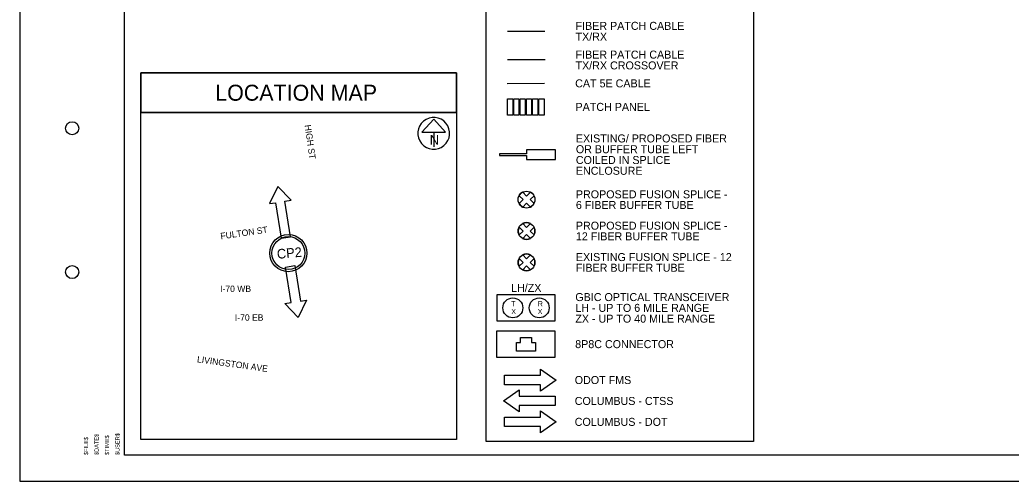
# Model space of a CAD drawing. Extents: x 1805893 to 1833564, y 708898 to 716199.
# Drawn here: x 1831322.5 to 1831701.4, y 713257.9 to 713434.4 of the extents above; entities that cross this region are included whole.
import ezdxf

# ---------------------------------------------------------------- set-up
doc = ezdxf.new("R2010")
doc.units = 0
for name, color, linetype in [('BR_X_Slab_Object', 7, 'Continuous'), ('SH_Border', 7, 'Continuous'), ('SH_Cut_Line', 7, 'Continuous'), ('SH_Data', 7, 'Continuous'), ('SH_Text', 7, 'Continuous'), ('UT_X_Misc_Cells', 7, 'Continuous')]:
    doc.layers.add(name, color=color, linetype=linetype)

msp = doc.modelspace()

# ---------------------------------------------------------------- linework, layer by layer
at = {"layer": 'SH_Border'}
msp.add_lwpolyline([(1831362.49, 713687.91), (1831992.49, 713687.91), (1831992.49, 713267.91), (1831362.49, 713267.91)], close=True, dxfattribs=at)
for centre in [(1831342.49, 713392.91), (1831342.49, 713337.91)]:
    msp.add_circle(centre, 2.5, dxfattribs=at)
at = {"layer": 'SH_Cut_Line'}
msp.add_lwpolyline([(1831322.49, 713257.91), (1832002.49, 713257.91), (1832002.49, 713697.91), (1831322.49, 713697.91)], close=True, dxfattribs=at)
at = {"layer": 'SH_Data'}
for p, q in [((1831508.86, 713430.01), (1831523.2, 713430.01)), ((1831514.81, 713365.61), (1831513.31, 713367.1)), ((1831513.31, 713367.1), (1831514.81, 713365.61)), ((1831516.16, 713366.96), (1831514.67, 713368.45)), ((1831516.16, 713366.96), (1831514.67, 713368.45)), ((1831516.16, 713366.96), (1831517.65, 713368.45)), ((1831517.65, 713368.45), (1831516.16, 713366.96)), ((1831517.52, 713365.61), (1831519.01, 713367.1)), ((1831517.52, 713365.61), (1831519.01, 713367.1)), ((1831513.31, 713364.11), (1831514.81, 713365.61)), ((1831514.81, 713365.61), (1831513.31, 713364.11)), ((1831514.67, 713362.76), (1831516.16, 713364.25)), ((1831514.67, 713362.76), (1831516.16, 713364.25)), ((1831517.65, 713362.76), (1831516.16, 713364.25)), ((1831516.16, 713364.25), (1831517.65, 713362.76)), ((1831519.01, 713364.11), (1831517.52, 713365.61)), ((1831519.01, 713364.11), (1831517.52, 713365.61)), ((1831514.81, 713353.6), (1831513.31, 713355.09)), ((1831514.81, 713353.6), (1831513.31, 713355.09)), ((1831516.16, 713354.95), (1831514.67, 713356.44)), ((1831514.67, 713356.44), (1831516.16, 713354.95)), ((1831516.16, 713354.95), (1831517.65, 713356.44)), ((1831516.16, 713354.95), (1831517.65, 713356.44)), ((1831517.52, 713353.6), (1831519.01, 713355.09)), ((1831519.01, 713355.09), (1831517.52, 713353.6)), ((1831513.31, 713352.1), (1831514.81, 713353.6)), ((1831513.31, 713352.1), (1831514.81, 713353.6)), ((1831514.67, 713350.75), (1831516.16, 713352.24)), ((1831516.16, 713352.24), (1831514.67, 713350.75)), ((1831517.65, 713350.75), (1831516.16, 713352.24)), ((1831517.65, 713350.75), (1831516.16, 713352.24)), ((1831519.01, 713352.1), (1831517.52, 713353.6)), ((1831517.52, 713353.6), (1831519.01, 713352.1)), ((1831516.16, 713342.95), (1831514.67, 713344.44)), ((1831514.67, 713344.44), (1831516.16, 713342.95)), ((1831516.16, 713342.95), (1831517.65, 713344.44)), ((1831516.16, 713342.95), (1831517.65, 713344.44)), ((1831514.81, 713341.59), (1831513.31, 713343.08)), ((1831514.81, 713341.59), (1831513.31, 713343.08)), ((1831513.31, 713340.1), (1831514.81, 713341.59)), ((1831513.31, 713340.1), (1831514.81, 713341.59)), ((1831514.67, 713338.74), (1831516.16, 713340.24)), ((1831516.16, 713340.24), (1831514.67, 713338.74)), ((1831517.65, 713338.74), (1831516.16, 713340.24)), ((1831517.65, 713338.74), (1831516.16, 713340.24)), ((1831517.52, 713341.59), (1831519.01, 713343.08)), ((1831519.01, 713343.08), (1831517.52, 713341.59)), ((1831519.01, 713340.1), (1831517.52, 713341.59)), ((1831517.52, 713341.59), (1831519.01, 713340.1)), ((1831507.7, 713298.4), (1831521.44, 713298.4)), ((1831507.7, 713294.8), (1831507.7, 713298.4)), ((1831521.44, 713298.4), (1831521.44, 713300.8)), ((1831521.44, 713294.8), (1831507.7, 713294.8)), ((1831521.44, 713292.4), (1831521.44, 713294.8)), ((1831513.37, 713292.8), (1831513.37, 713290.4)), ((1831513.37, 713290.4), (1831527.11, 713290.4)), ((1831527.11, 713286.8), (1831513.37, 713286.8)), ((1831513.37, 713286.8), (1831513.37, 713284.4)), ((1831527.11, 713290.4), (1831527.11, 713286.8)), ((1831521.44, 713282.4), (1831521.44, 713284.8)), ((1831507.7, 713282.4), (1831521.44, 713282.4)), ((1831507.7, 713278.8), (1831507.7, 713282.4)), ((1831521.44, 713278.8), (1831507.7, 713278.8)), ((1831521.44, 713276.4), (1831521.44, 713278.8))]:
    msp.add_line(p, q, dxfattribs=at)
for points in [[(1831602.93, 713463.24), (1831602.93, 713273.07), (1831500.7, 713273.07), (1831500.7, 713463.24)], [(1831489.36, 713414.04), (1831368.72, 713414.04), (1831368.72, 713398.93), (1831489.36, 713398.93)], [(1831489.36, 713398.93), (1831368.72, 713398.93), (1831368.72, 713414.04), (1831489.36, 713414.04)], [(1831510.87, 713404.19), (1831510.87, 713397.94), (1831508.91, 713397.94), (1831508.91, 713404.19)], [(1831513.26, 713404.19), (1831513.26, 713397.94), (1831511.3, 713397.94), (1831511.3, 713404.19)], [(1831515.66, 713404.19), (1831515.66, 713397.94), (1831513.7, 713397.94), (1831513.7, 713404.19)], [(1831518.05, 713404.19), (1831518.05, 713397.94), (1831516.09, 713397.94), (1831516.09, 713404.19)], [(1831520.45, 713404.19), (1831520.45, 713397.94), (1831518.49, 713397.94), (1831518.49, 713404.19)], [(1831522.85, 713404.19), (1831522.85, 713397.94), (1831520.88, 713397.94), (1831520.88, 713404.19)], [(1831489.36, 713398.93), (1831489.36, 713273.91), (1831368.72, 713273.91), (1831368.72, 713398.93)], [(1831489.36, 713398.93), (1831489.36, 713273.91), (1831368.72, 713273.91), (1831368.72, 713398.93)], [(1831489.36, 713398.93), (1831489.36, 713273.91), (1831368.72, 713273.91), (1831368.72, 713398.93)], [(1831489.36, 713398.93), (1831489.36, 713273.91), (1831368.72, 713273.91), (1831368.72, 713398.93)], [(1831504.91, 713329.33), (1831527, 713329.33), (1831527, 713319.08), (1831504.91, 713319.08)], [(1831504.85, 713315.45), (1831526.95, 713315.45), (1831526.95, 713305.2), (1831504.85, 713305.2)]]:
    msp.add_lwpolyline(points, close=True, dxfattribs=at)
for points in [[(1831523.23, 713419.01), (1831508.86, 713419.01), (1831508.86, 713419.01), (1831508.86, 713419.01)], [(1831508.72, 713410.07), (1831523.06, 713410.1), (1831523.06, 713410.1)], [(1831505.86, 713383.13), (1831505.86, 713382.82), (1831505.86, 713382.52), (1831516.15, 713382.52), (1831516.15, 713380.99), (1831527.2, 713380.99), (1831527.2, 713384.66), (1831516.15, 713384.66), (1831516.15, 713383.13), (1831505.86, 713383.13)], [(1831527.2, 713380.99), (1831527.2, 713384.66), (1831516.15, 713384.66), (1831516.15, 713383.13), (1831505.86, 713383.13), (1831505.86, 713382.82), (1831505.86, 713382.52), (1831516.15, 713382.52), (1831516.15, 713380.99), (1831527.2, 713380.99)], [(1831518.03, 713310.93), (1831519.54, 713310.93), (1831519.54, 713307.7), (1831512.27, 713307.7), (1831512.27, 713310.93), (1831513.78, 713310.93)], [(1831513.78, 713310.93), (1831513.78, 713312.84), (1831518.03, 713312.84), (1831518.03, 713310.93)], [(1831521.44, 713300.8), (1831527.44, 713296.6), (1831521.44, 713292.4)], [(1831513.37, 713284.4), (1831507.37, 713288.6), (1831513.37, 713292.8)], [(1831521.44, 713284.8), (1831527.44, 713280.6), (1831521.44, 713276.4)]]:
    msp.add_lwpolyline(points, dxfattribs=at)
for centre, radius in [((1831516.16, 713365.61), 3.22), ((1831516.16, 713353.6), 3.22), ((1831516.16, 713341.59), 3.22), ((1831510.91, 713324.2), 3.81), ((1831521, 713324.2), 3.81)]:
    msp.add_circle(centre, radius, dxfattribs=at)
for centre, start, end in [((1831516.16, 713365.61), 117.647, 152.353), ((1831516.16, 713365.61), 27.647, 62.353), ((1831516.16, 713365.61), 207.647, 242.353), ((1831516.16, 713365.61), 297.647, 332.353), ((1831516.16, 713353.6), 152.353, 207.647), ((1831516.16, 713353.6), 62.353, 117.647), ((1831516.16, 713353.6), 332.353, 27.647), ((1831516.16, 713353.6), 242.353, 297.647), ((1831516.16, 713341.59), 62.353, 117.647), ((1831516.16, 713341.59), 152.353, 207.647), ((1831516.16, 713341.59), 332.353, 27.647), ((1831516.16, 713341.59), 242.353, 297.647)]:
    msp.add_arc(centre, 3.22, start, end, dxfattribs=at)
at = {"layer": 'SH_Text'}
for p, q in [((1831480.69, 713396.42), (1831476.18, 713391.42)), ((1831485.19, 713391.42), (1831480.69, 713396.42)), ((1831476.18, 713391.42), (1831485.19, 713391.42)), ((1831480.69, 713391.42), (1831480.69, 713385.76)), ((1831417.86, 713364.06), (1831420.23, 713364.43)), ((1831420.23, 713364.43), (1831422.33, 713350.86)), ((1831423.79, 713364.98), (1831426.16, 713365.35)), ((1831425.89, 713351.41), (1831423.79, 713364.98)), ((1831422.33, 713350.86), (1831425.89, 713351.41)), ((1831424.05, 713339.8), (1831427.61, 713340.35)), ((1831427.61, 713340.35), (1831429.71, 713326.78)), ((1831426.16, 713326.23), (1831424.05, 713339.8)), ((1831423.78, 713325.86), (1831426.16, 713326.23)), ((1831429.71, 713326.78), (1831432.08, 713327.15))]:
    msp.add_line(p, q, dxfattribs=at)
for points in [[(1831426.16, 713365.35), (1831421.09, 713370.64), (1831417.86, 713364.06)], [(1831432.08, 713327.15), (1831428.85, 713320.57), (1831423.78, 713325.86)]]:
    msp.add_lwpolyline(points, dxfattribs=at)
for radius in [7.11, 6.31]:
    msp.add_circle((1831425.13, 713345.15), radius, dxfattribs=at)
msp.add_arc((1831480.69, 713390.95), 6.08, 129.7798, 129.7633, dxfattribs=at)

# ---------------------------------------------------------------- texts
at = {"layer": 'BR_X_Slab_Object'}
for s, p in [('T', (1831510.3, 713324.8)), ('R', (1831520.4, 713324.8)), ('X', (1831510.3, 713321.8)), ('X', (1831520.4, 713321.8))]:
    msp.add_text(s, height=2, rotation=0.0475, dxfattribs=at).set_placement(p)
at = {"layer": 'SH_Data'}
for s, height, p in [('FIBER PATCH CABLE', 3.0596, (1831534.88, 713430.54)), ('TX/RX', 3.06, (1831534.88, 713426.42)), ('FIBER PATCH CABLE', 3.0596, (1831534.88, 713419.54)), ('TX/RX CROSSOVER', 3.0596, (1831534.88, 713415.41)), ('LOCATION MAP', 6.1191, (1831397.18, 713403.43)), ('CAT 5E CABLE', 3.0596, (1831534.74, 713408.54)), ('PATCH PANEL', 3.0596, (1831534.86, 713399.54)), ('EXISTING/ PROPOSED FIBER ', 3.0596, (1831535, 713387.48)), ('OR BUFFER TUBE LEFT ', 3.0596, (1831535, 713383.35)), ('COILED IN SPLICE ', 3.0596, (1831535, 713379.23)), ('ENCLOSURE', 3.06, (1831535, 713375.11)), ('PROPOSED FUSION SPLICE - ', 3.0596, (1831535.01, 713366.11)), ('6 FIBER BUFFER TUBE', 3.0596, (1831535.01, 713362.03)), ('PROPOSED FUSION SPLICE - ', 3.0596, (1831535.01, 713354.11)), ('12 FIBER BUFFER TUBE', 3.0596, (1831535.01, 713350.03)), ('EXISTING FUSION SPLICE - 12 ', 3.0596, (1831535.01, 713342.1)), ('FIBER BUFFER TUBE', 3.0596, (1831535.01, 713338.03)), ('LH/ZX', 3.06, (1831510.23, 713330.33)), ('GBIC OPTICAL TRANSCEIVER', 3.0596, (1831534.8, 713326.8)), ('LH - UP TO 6 MILE RANGE', 3.0596, (1831534.8, 713322.67)), ('ZX - UP TO 40 MILE RANGE', 3.0596, (1831534.8, 713318.55)), ('8P8C CONNECTOR', 3.0596, (1831534.75, 713308.8)), ('ODOT FMS', 3.06, (1831534.57, 713295.07)), ('COLUMBUS - CTSS', 3.0596, (1831534.57, 713287.07)), ('COLUMBUS - DOT', 3.0596, (1831534.57, 713279.07))]:
    msp.add_text(s, height=height, dxfattribs=at).set_placement(p)
at = {"layer": 'SH_Text'}
for s, height, rotation, p in [('HIGH ST', 2.448, 278.061, (1831431.33, 713394.08)), ('N', 3.66, 360, (1831479.17, 713386.68)), ('FULTON ST', 2.448, 8.061, (1831399.34, 713350.41)), ('CP2', 3.671, 5, (1831420.9, 713342.94)), ('I-70 WB', 2.448, 0.3445, (1831399.05, 713330.24)), ('I-70 EB', 2.448, 0.3445, (1831404.69, 713319.23)), ('LIVINGSTON AVE', 2.4477, 352.086, (1831390.1, 713303.41))]:
    msp.add_text(s, height=height, rotation=rotation, dxfattribs=at).set_placement(p)
at = {"layer": 'UT_X_Misc_Cells'}
for s, p in [('$DATE$', (1831352.59, 713267.91)), ('$USER$', (1831360.59, 713267.91)), ('$FILE$', (1831348.59, 713267.91)), ('$TIME$', (1831356.59, 713267.91))]:
    msp.add_text(s, height=1.56, rotation=90, dxfattribs=at).set_placement(p)

doc.saveas('drawing.dxf')
